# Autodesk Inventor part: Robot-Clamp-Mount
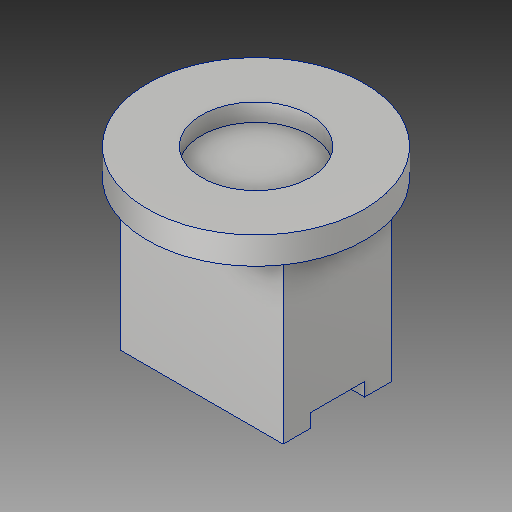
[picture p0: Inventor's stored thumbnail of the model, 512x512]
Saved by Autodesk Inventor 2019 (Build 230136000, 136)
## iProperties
Created: 2018-07
Part Number: Robot-Clamp-Mount
Material: Aluminum 6061
Description: 123456
Document SubType Name: Modeling
Designer: Power User
Mass: 486.263 g
Surface Area: 257.832 cm^2
Volume: 180.097 cm^3
Density: 2.7 g/cm^3
Appearance: Aluminum - Flat
Title: GEAR
Author: Power User
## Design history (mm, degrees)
sketch "Sketch6"
  geometry: L1 (60, 20)-(0, 20); L2 (0, -20)-(60, -20); L3 (60, -20)-(60, 20); L4 (0, 10)-(5, 10); L5 (5, 10)-(5, -10); L6 (5, -10)-(0, -10); L7 (0, 20)-(0, 10); L8 (0, -10)-(0, -20); 4 further points
  constraints: 16 end point, 7 perpendicular, 3 parallel, 2 coincident, 2 horizontal alignment, 2 midpoint, 2 vertical alignment, 1 horizontal
  dimensions: "d44" = 40 distance between parallel lines of L2 L1; "d45" = 20 distance of L4.end L5.end; "d46" = 5 distance from line of L5 point (0, 0); "d47" = 60 distance from line of point (0, 0) L3
extrude "Extrusion5" new body sketch "Sketch6" stored distance "d48" = 60; taper "d49" = 0 deg
sketch "Sketch7"
  geometry: C1 r 40 at (30, 20); 1 further point
  constraints: 1 centre point, 1 coincident
  dimensions: "d50" = 80 diameter of C1
extrude "Extrusion6" join sketch "Sketch7" distance "d51" = 10; taper "d52" = 0 deg
sketch "Sketch8"
  geometry: C1 r 40 at (0, 0) reference; 2 further points
  constraints: 1 coincident
hole "Hole2" sketch "Sketch8" at (0, 0) diameter "d53" = 40; stored, may be unused: countersink angle "d57" = 90 deg, drill point angle "d59" = 0 deg; dims "d54" = 6, "d55" = 4, "d56" = 2, "d58" = 6.5
body "Solid2"
